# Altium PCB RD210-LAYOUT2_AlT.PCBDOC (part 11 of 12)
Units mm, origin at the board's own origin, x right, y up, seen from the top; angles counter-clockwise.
Board outline 250 x 123 mm, 4 copper layers (TOP, Mid-Layer 1, Mid-Layer 2, BOTTOM), stack 0.711 mm thick; 1043 components, 659 nets, 2786 pads, 1228 vias.
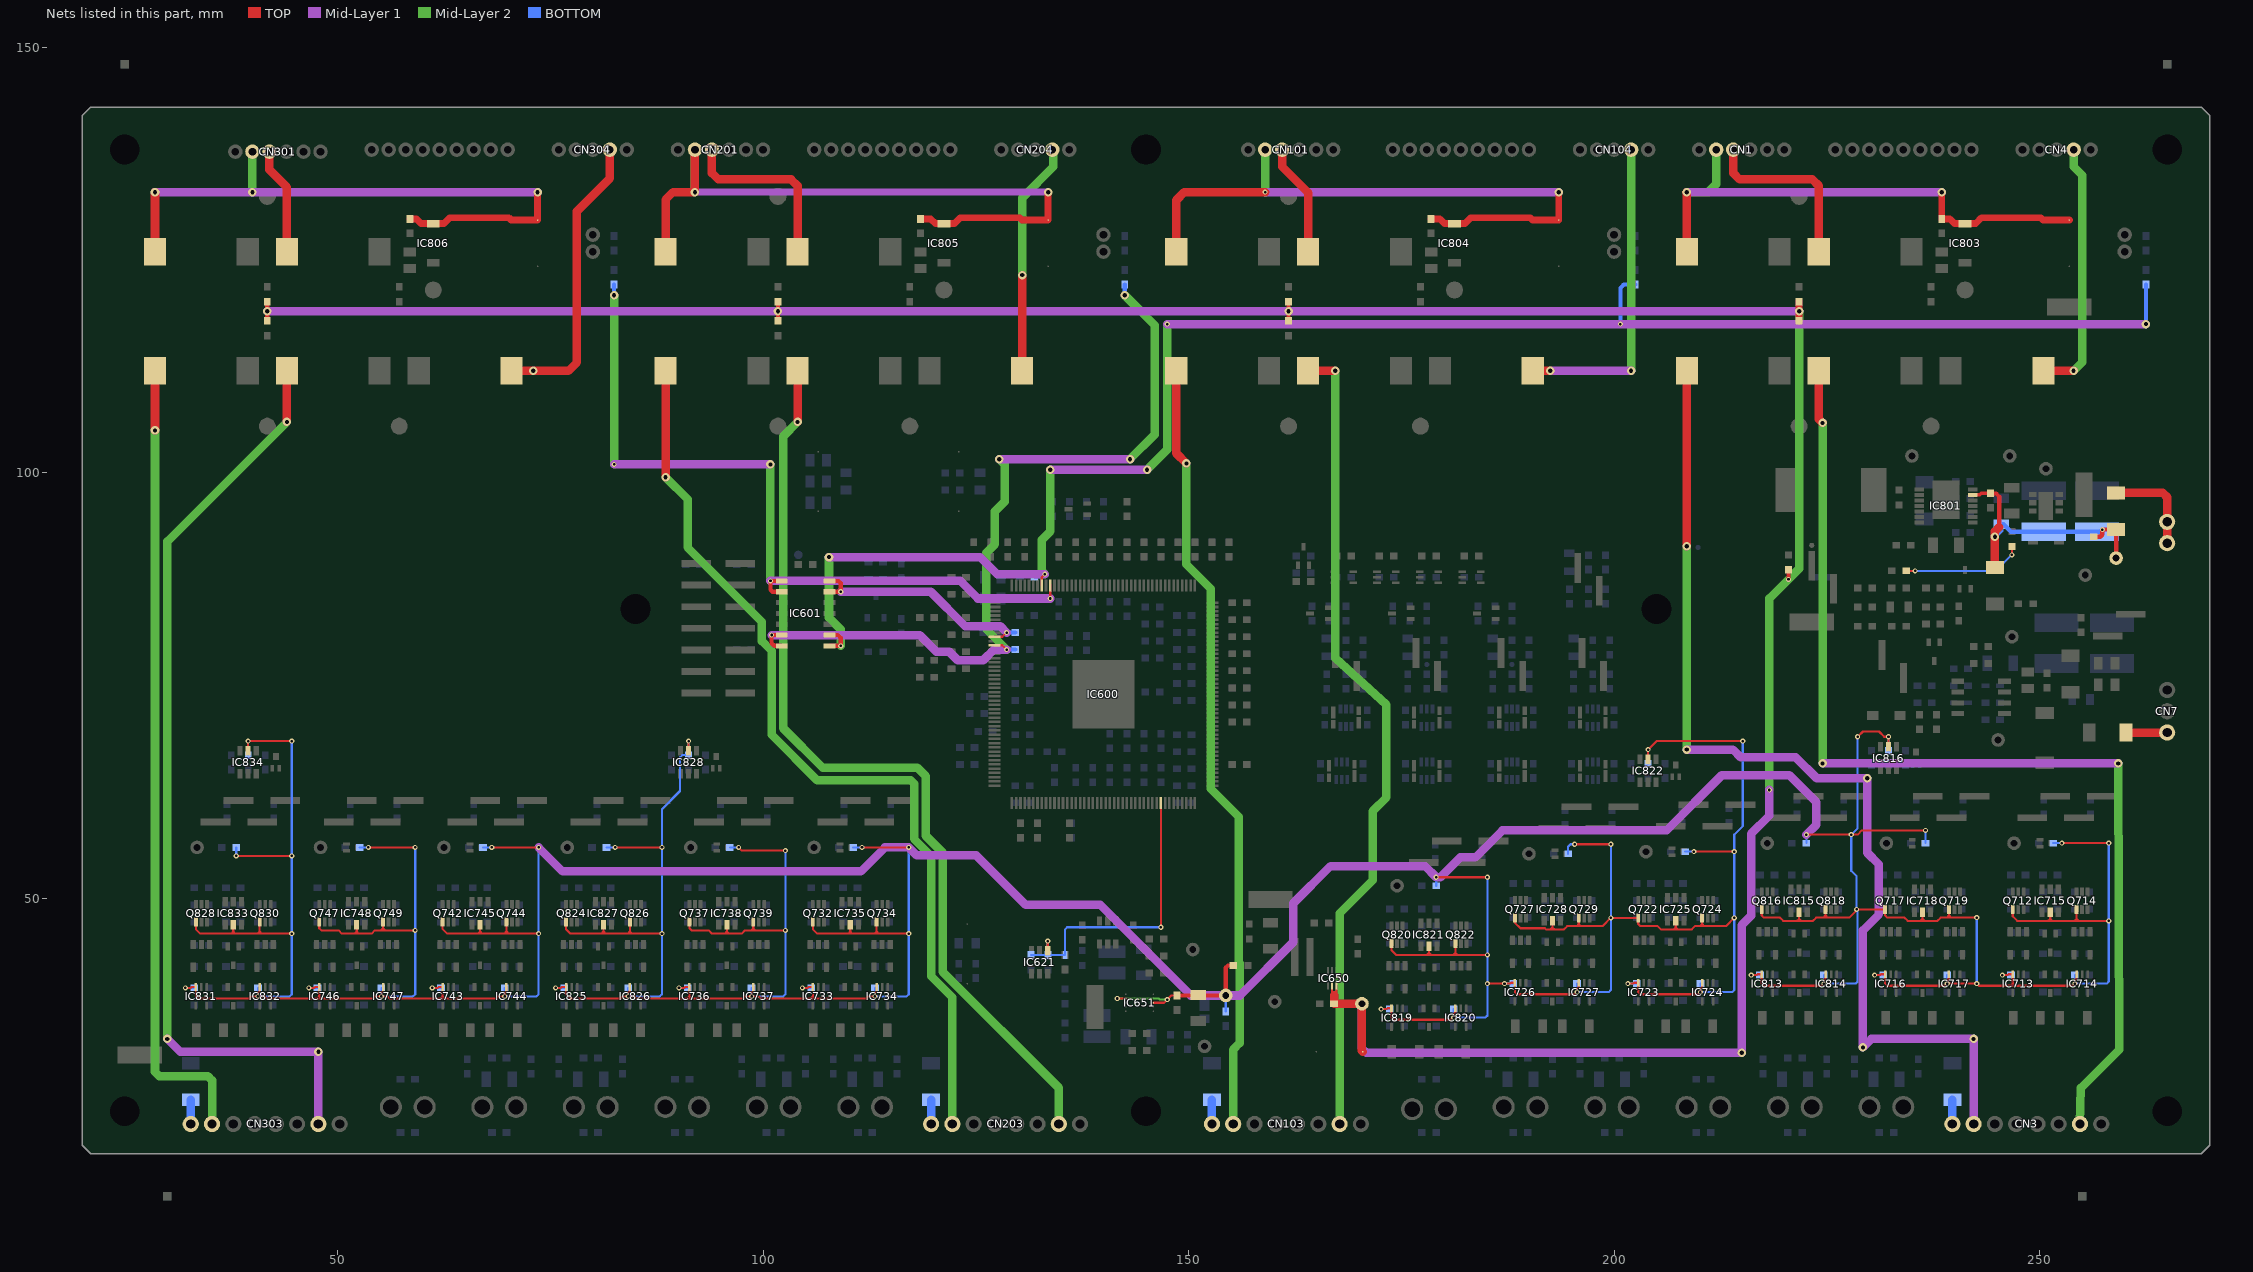
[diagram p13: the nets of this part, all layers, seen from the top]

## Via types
v1: diameter 0.6, hole 0.3, TOP to BOTTOM, 1134 vias
v2: diameter 1, hole 0.5, TOP to BOTTOM, 94 vias

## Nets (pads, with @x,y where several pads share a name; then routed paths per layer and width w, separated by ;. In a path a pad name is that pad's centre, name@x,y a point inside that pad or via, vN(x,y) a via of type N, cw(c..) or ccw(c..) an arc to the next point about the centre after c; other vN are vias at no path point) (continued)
VP_5R0-1234: ?.1 C701.2 C702.2 C716.1 C717.1 C718.1 C726.1 C727.1 C728.1 C736.1 C737.1 C738.1 C746.1 C747.1 C748.1 C756.1 C757.1 C758.1 C766.1 C767.1 C768.1 C776.1 C777.1 C778.1 C786.1 C787.1 C916.1 C917.1 C918.1 C919.1 C926.1 C927.1 C928.1 C929.1 C936.1 C937.1 C938.1 C939.1 C946.1 C947.1 C948.1 C949.1 CN959.1 IC651.3 IC651.7 IC713.3 IC714.3 IC715.5 IC716.3 IC717.3 IC718.5 IC723.3 IC724.3 IC725.5 IC726.3 IC727.3 IC728.5 IC733.3 IC734.3 IC735.5 IC736.3 IC737.3 IC738.5 IC743.3 IC744.3 IC745.5 IC746.3 IC747.3 IC748.5 IC813.3 IC814.3 IC815.5 IC816.5 IC819.3 IC820.3 IC821.5 IC822.5 IC825.3 IC826.3 IC827.5 IC828.5 IC831.3 IC832.3 IC833.5 IC834.5 J826.2 Q712.1 Q714.1 Q717.1 Q719.1 Q722.1 Q724.1 Q727.1 Q729.1 Q732.1 Q734.1 Q737.1 Q739.1 Q742.1 Q744.1 Q747.1 Q749.1 Q816.1 Q818.1 Q820.1 Q822.1 Q824.1 Q826.1 Q828.1 Q830.1 R674.1 | length 997.2
  TOP w0.25: v1(32.125,39.5) 32.775,39.5 32.875,39.6 IC831.3@33.35,39.6 33.35,38.5 33.6,38.25 39.625,38.25 39.875,38.5 v1(40.65,38.5) ; Q828.1@33.35,47.225 33.35,46.4 33.875,45.875 37.5,45.875 ; IC833.5@37.75,46.9 37.75,46.125 ; v1(38.1,55) v1(44.625,55) ; IC834.5@39.5,67.35 v1(39.5,68.5) v1(44.625,68.5) ; IC832.3@40.85,39.6 40.85,39.125 40.65,38.925 v1(40.65,38.5) ; Q830.1@40.85,47.225 40.85,46.125 ; v1(44.625,45.875) 41.1,45.875 ; v1(46.625,39.5) 47.275,39.5 47.375,39.6 IC746.3@47.85,39.6 47.85,38.5 ; Q747.1@47.85,47.225 47.85,46.5 48.1,46.25 50.125,46.25 50.5,45.875 52,45.875 ; IC748.5@52.25,46.9 52.25,46.125 ; v1(53.625,56) v1(59.125,56) ; IC747.3@55.35,39.6 55.35,39.125 55.15,38.925 v1(55.15,38.5) ; Q749.1@55.35,47.225 55.35,46.5 ; v1(59.125,46.25) 55.6,46.25 ; v1(61.125,39.5) 61.775,39.5 61.875,39.6 IC743.3@62.35,39.6 62.35,38.5 ; Q742.1@62.35,47.225 62.35,46.4 62.875,45.875 66.5,45.875 ; IC745.5@66.75,46.9 66.75,46.125 ; v1(68.125,56) v1(73.625,56) ; IC744.3@69.85,39.6 69.85,39.125 69.65,38.925 v1(69.65,38.5) 68.875,38.5 68.625,38.25 62.6,38.25 ; Q744.1@69.85,47.225 69.85,46.125 ; v1(73.625,45.875) 70.1,45.875 ; v1(75.625,39.5) 76.275,39.5 76.375,39.6 IC825.3@76.85,39.6 76.85,38.75 77.35,38.25 83.25,38.25 83.5,38.5 v1(84.15,38.5) ; Q824.1@76.85,47.225 76.85,46.4 77.375,45.875 81,45.875 ; IC827.5@81.25,46.9 81.25,46.125 ; v1(82.625,56) v1(88.125,56) ; IC826.3@84.35,39.6 84.35,39.125 84.15,38.925 v1(84.15,38.5) ; Q826.1@84.35,47.225 84.35,46.125 ; v1(88.125,45.875) 84.6,45.875 ; v1(90.125,39.5) 90.775,39.5 90.875,39.6 IC736.3@91.35,39.6 91.35,38.5 ; IC828.5@91.25,67.35 v1(91.25,68.5) ; Q737.1@91.35,47.225 91.35,46.5 91.6,46.25 93.625,46.25 94,45.875 95.5,45.875 ; IC738.5@95.75,46.9 95.75,46.125 ; v1(97.125,56) 97.5,55.625 v1(102.625,55.625) ; IC737.3@98.85,39.6 98.85,39.125 98.65,38.925 v1(98.65,38.5) ; Q739.1@98.85,47.225 98.85,46.5 ; v1(102.625,46.25) 99.1,46.25 ; v1(104.625,39.5) 105.275,39.5 105.375,39.6 IC733.3@105.85,39.6 105.85,38.5 ; Q732.1@105.85,47.225 105.85,46.4 106.375,45.875 110,45.875 ; IC735.5@110.25,46.9 110.25,46.125 ; v1(111.625,56) v1(117.125,56) ; IC734.3@113.35,39.6 113.35,39.125 113.15,38.925 v1(113.15,38.5) 112.375,38.5 112.125,38.25 106.1,38.25 ; Q734.1@113.35,47.225 113.35,46.125 ; v1(117.125,45.875) 113.6,45.875 ; v1(141.625,38.25) IC651.7@142.625,38.25 ; IC651.3@145.875,37.75 147.125,37.75 v1(147.5,38.125) 147.975,38.6 C702.2@148.625,38.6 ; C701.2@151.075,38.6 C701.2@151.125,38.65 ; v1(172.625,37) 173.275,37 173.375,37.1 IC819.3@173.85,37.1 173.85,36 174.1,35.75 180.9,35.75 v1(181.15,36) 181.15,36.425 181.35,36.625 IC820.3@181.35,37.1 ; Q820.1@173.85,44.725 173.85,43.9 174.375,43.375 178,43.375 ; IC821.5@178.25,44.4 178.25,43.625 ; v1(179.1,52.5) v1(185.125,52.5) ; Q822.1@181.35,44.725 181.35,43.625 ; v1(185.125,40) v1(187.125,40) 187.775,40 187.875,40.1 IC726.3@188.35,40.1 188.35,39 188.6,38.75 195.4,38.75 v1(195.65,39) 195.65,39.425 195.85,39.625 IC727.3@195.85,40.1 ; v1(185.125,43.375) 181.6,43.375 ; Q727.1@188.35,47.725 188.35,47.15 189,46.5 191.875,46.5 192,46.375 192.5,46.375 ; IC728.5@192.75,47.4 192.75,46.625 ; v1(195.375,56.375) v1(199.625,56.375) ; Q729.1@195.85,47.725 195.85,47 ; v1(201.625,40) 202.275,40 202.375,40.1 IC723.3@202.85,40.1 202.85,39 203.1,38.75 209.9,38.75 v1(210.15,39) 210.15,39.425 210.35,39.625 IC724.3@210.35,40.1 ; IC822.5@204,66.35 v1(204,67.5) 205,68.5 v1(215.125,68.5) ; IC725.5@207.25,47.4 207.25,46.625 ; v1(209.375,55.5) v1(214.125,55.5) ; Q724.1@210.35,47.725 210.35,47 ; v1(214.125,47.725) 213.15,46.75 210.6,46.75 ; v1(216.125,41) 216.775,41 216.875,41.1 IC813.3@217.35,41.1 217.35,40 217.6,39.75 224.4,39.75 v1(224.65,40) 224.65,40.425 224.85,40.625 IC814.3@224.85,41.1 ; Q816.1@217.35,48.725 217.35,48 217.6,47.75 219.5,47.75 219.875,47.375 221.5,47.375 ; IC815.5@221.75,48.4 221.75,47.625 ; v1(222.6,57.5) v1(227.875,57.5) 228.625,57.5 229.125,58 v1(236.6,58) ; Q818.1@224.85,48.725 224.85,48 ; v1(228.625,69) 229.25,69.625 231.125,69.625 231.75,69 v1(232.25,69) IC816.5@232.25,67.85 ; v1(230.625,41) 231.275,41 231.375,41.1 IC716.3@231.85,41.1 231.85,40 232.1,39.75 238.9,39.75 v1(239.15,40) ; IC718.5@236.25,48.4 236.25,47.625 ; IC717.3@239.35,41.1 239.35,40.625 239.15,40.425 v1(239.15,40) ; Q719.1@239.35,48.725 239.35,48 ; v1(242.625,47.75) 239.6,47.75 ; v1(245.625,41) 246.275,41 246.375,41.1 IC713.3@246.85,41.1 246.85,40 ; Q712.1@246.85,48.725 246.85,47.9 247.375,47.375 251,47.375 ; IC715.5@251.25,48.4 251.25,47.625 ; v1(252.625,56.5) v1(258.125,56.5) ; IC714.3@254.35,41.1 254.35,40.625 254.15,40.425 v1(254.15,40) 253.9,39.75 247.1,39.75 ; Q714.1@254.35,48.725 254.35,47.625 ; v1(258.125,47.375) 254.6,47.375 ; 37.5,45.875 38,45.875 ; 37.5,45.875 37.75,46.125 ; 37.75,46.125 38,45.875 ; 38,45.875 40.6,45.875 ; 40.6,45.875 41.1,45.875 ; 40.6,45.875 40.85,46.125 ; v1(40.65,38.5) 41.375,38.5 41.625,38.25 47.6,38.25 ; 40.85,46.125 41.1,45.875 ; 47.6,38.25 47.85,38.5 ; 47.6,38.25 48.1,38.25 ; 47.85,38.5 48.1,38.25 ; 48.1,38.25 54.125,38.25 54.375,38.5 v1(55.15,38.5) ; 52,45.875 52.25,46.125 ; 52,45.875 52.5,45.875 ; 52.25,46.125 52.5,45.875 ; 52.5,45.875 54,45.875 54.375,46.25 55.1,46.25 ; 55.1,46.25 55.6,46.25 ; 55.1,46.25 55.35,46.5 ; v1(55.15,38.5) 55.875,38.5 56.125,38.25 62.1,38.25 ; 55.35,46.5 55.6,46.25 ; 62.1,38.25 62.35,38.5 ; 62.1,38.25 62.6,38.25 ; 62.35,38.5 62.6,38.25 ; 66.5,45.875 67,45.875 ; 66.5,45.875 66.75,46.125 ; 66.75,46.125 67,45.875 ; 67,45.875 69.6,45.875 ; 69.6,45.875 70.1,45.875 ; 69.6,45.875 69.85,46.125 ; 69.85,46.125 70.1,45.875 ; 81,45.875 81.5,45.875 ; 81,45.875 81.25,46.125 ; 81.25,46.125 81.5,45.875 ; 81.5,45.875 84.1,45.875 ; 84.1,45.875 84.6,45.875 ; 84.1,45.875 84.35,46.125 ; v1(84.15,38.5) 84.875,38.5 85.125,38.25 91.1,38.25 ; 84.35,46.125 84.6,45.875 ; 91.1,38.25 91.35,38.5 ; 91.1,38.25 91.6,38.25 ; 91.35,38.5 91.6,38.25 ; 91.6,38.25 97.625,38.25 97.875,38.5 v1(98.65,38.5) ; 95.5,45.875 96,45.875 ; 95.5,45.875 95.75,46.125 ; 95.75,46.125 96,45.875 ; 96,45.875 97.5,45.875 97.875,46.25 98.6,46.25 ; 98.6,46.25 99.1,46.25 ; 98.6,46.25 98.85,46.5 ; v1(98.65,38.5) 99.5,38.5 99.75,38.25 105.6,38.25 ; 98.85,46.5 99.1,46.25 ; 105.6,38.25 105.85,38.5 ; 105.6,38.25 106.1,38.25 ; 105.85,38.5 106.1,38.25 ; 110,45.875 110.5,45.875 ; 110,45.875 110.25,46.125 ; 110.25,46.125 110.5,45.875 ; 110.5,45.875 113.1,45.875 ; 113.1,45.875 113.6,45.875 ; 113.1,45.875 113.35,46.125 ; 113.35,46.125 113.6,45.875 ; 178,43.375 178.5,43.375 ; 178,43.375 178.25,43.625 ; 178.25,43.625 178.5,43.375 ; 178.5,43.375 181.1,43.375 ; 181.1,43.375 181.6,43.375 ; 181.1,43.375 181.35,43.625 ; 181.35,43.625 181.6,43.375 ; 192.5,46.375 192.75,46.625 ; 192.5,46.375 193,46.375 ; 192.75,46.625 193,46.375 ; 193,46.375 194.125,46.375 194.5,46.75 195.6,46.75 ; 195.6,46.75 195.85,47 ; 195.6,46.75 196.1,46.75 ; 195.85,47 196.1,46.75 ; 196.1,46.75 198.65,46.75 v1(199.625,47.725) Q722.1@202.85,47.725 202.85,47 203.1,46.75 205.125,46.75 205.5,46.375 207,46.375 ; 207,46.375 207.5,46.375 ; 207,46.375 207.25,46.625 ; 207.25,46.625 207.5,46.375 ; 207.5,46.375 209.125,46.375 209.5,46.75 210.1,46.75 ; 210.1,46.75 210.6,46.75 ; 210.1,46.75 210.35,47 ; 210.35,47 210.6,46.75 ; 221.5,47.375 222,47.375 ; 221.5,47.375 221.75,47.625 ; 221.75,47.625 222,47.375 ; 222,47.375 223.375,47.375 223.75,47.75 224.6,47.75 ; 224.6,47.75 225.1,47.75 ; 224.6,47.75 224.85,48 ; 224.85,48 225.1,47.75 ; 225.1,47.75 227.65,47.75 228.5,48.6 v1(228.5,48.725) Q717.1@231.85,48.725 231.85,48 232.1,47.75 234.125,47.75 234.5,47.375 236,47.375 ; 236,47.375 236.5,47.375 ; 236,47.375 236.25,47.625 ; 236.25,47.625 236.5,47.375 ; 236.5,47.375 238,47.375 238.375,47.75 239.1,47.75 ; 239.1,47.75 239.6,47.75 ; 239.1,47.75 239.35,48 ; v1(239.15,40) v1(242.625,40) 242.875,39.75 246.6,39.75 ; 239.35,48 239.6,47.75 ; 246.6,39.75 246.85,40 ; 246.6,39.75 247.1,39.75 ; 246.85,40 247.1,39.75 ; 251,47.375 251.5,47.375 ; 251,47.375 251.25,47.625 ; 251.25,47.625 251.5,47.375 ; 251.5,47.375 254.1,47.375 ; 254.1,47.375 254.6,47.375 ; 254.1,47.375 254.35,47.625 ; 254.35,47.625 254.6,47.375
  TOP w0.5: C702.2@148.625,38.6 C701.2@151.075,38.6 ; C701.2@151.125,38.65 151.175,38.6 CN959.1@154.375,38.6 154.375,41.875 154.625,42.125 J826.2@155.25,42.125
  Mid-Layer 1 w1: v1(73.625,56) 76.445,53.18 111.504,53.18 114.324,56 v1(117.125,56) 118.04,55.085 125.025,55.085 130.871,49.239 139.638,49.239 150.277,38.6 CN959.1@154.375,38.6 156.042,38.6 162.304,44.861 162.304,49.433 166.685,53.815 177.785,53.815 v1(179.1,52.5) 179.594,52.5 181.925,54.831 183.703,54.831 186.878,58.006 206.182,58.006 212.659,64.483 220.597,64.483 223.772,61.308 223.772,58.672 v1(222.6,57.5)
  Mid-Layer 2 w0.25: v1(141.625,38.25) 146.5,38.25 146.625,38.125 v1(147.5,38.125)
  BOTTOM w0.25: v1(32.125,39.5) C946.1@33.15,39.5 ; v1(38.1,55) C948.1@38.1,56 ; C949.1@39.5,66.85 v1(39.5,68.5) ; C947.1@40.65,39.5 v1(40.65,38.5) 44.375,38.5 44.625,38.75 v1(44.625,45.875) v1(44.625,55) v1(44.625,68.5) ; v1(46.625,39.5) C786.1@47.65,39.5 ; ?.1@52.6,56 v1(53.625,56) ; C787.1@55.15,39.5 v1(55.15,38.5) 58.875,38.5 59.125,38.75 v1(59.125,46.25) v1(59.125,56) ; v1(61.125,39.5) C776.1@62.15,39.5 ; C778.1@67.1,56 v1(68.125,56) ; C777.1@69.65,39.5 v1(69.65,38.5) 73.375,38.5 73.625,38.75 v1(73.625,45.875) v1(73.625,56) ; v1(75.625,39.5) C936.1@76.65,39.5 ; C938.1@81.6,56 v1(82.625,56) ; C937.1@84.15,39.5 v1(84.15,38.5) 87.875,38.5 88.125,38.75 v1(88.125,45.875) v1(88.125,56) 88.125,60.5 90.25,62.625 90.25,66.6 90.5,66.85 C939.1@91.25,66.85 v1(91.25,68.5) ; v1(90.125,39.5) C766.1@91.15,39.5 ; C768.1@96.1,56 v1(97.125,56) ; C767.1@98.65,39.5 v1(98.65,38.5) 102.375,38.5 102.625,38.75 v1(102.625,46.25) v1(102.625,55.625) ; v1(104.625,39.5) C756.1@105.65,39.5 ; C758.1@110.6,56 v1(111.625,56) ; C757.1@113.15,39.5 v1(113.15,38.5) 116.875,38.5 117.125,38.75 v1(117.125,45.875) v1(117.125,56) ; R674.1@154.375,36.725 CN959.1@154.375,38.6 ; v1(172.625,37) C926.1@173.65,37 ; C928.1@179.1,51.5 v1(179.1,52.5) ; C927.1@181.15,37 v1(181.15,36) 184.875,36 185.125,36.25 v1(185.125,40) v1(185.125,43.375) v1(185.125,52.5) ; v1(187.125,40) C746.1@188.15,40 ; C748.1@194.6,55.25 194.6,56.1 194.875,56.375 v1(195.375,56.375) ; C747.1@195.65,40 v1(195.65,39) 199.375,39 199.625,39.25 v1(199.625,47.725) v1(199.625,56.375) ; v1(201.625,40) C736.1@202.65,40 ; C929.1@204,65.85 v1(204,67.5) ; C738.1@208.35,55.5 v1(209.375,55.5) ; C737.1@210.15,40 v1(210.15,39) 213.875,39 214.125,39.25 v1(214.125,47.725) v1(214.125,55.5) 214.125,57.5 215.125,58.5 v1(215.125,68.5) ; v1(216.125,41) C916.1@217.15,41 ; C918.1@222.6,56.5 v1(222.6,57.5) ; C917.1@224.65,41 v1(224.65,40) 228.375,40 228.625,40.25 228.625,48.6 v1(228.5,48.725) 228.5,52.625 227.875,53.25 v1(227.875,57.5) 228.625,58.25 v1(228.625,69) ; v1(230.625,41) C726.1@231.65,41 ; C919.1@232.25,67.35 v1(232.25,69) ; C728.1@236.6,56.5 v1(236.6,58) ; v1(239.15,40) C727.1@239.15,41 ; v1(242.625,40) v1(242.625,47.75) ; v1(245.625,41) C716.1@246.65,41 ; C718.1@251.6,56.5 v1(252.625,56.5) ; C717.1@254.15,41 v1(254.15,40) 257.875,40 258.125,40.25 v1(258.125,47.375) v1(258.125,56.5)
VP_5R0_SYS: J828.1 R817.2 | length 14.2
  TOP w0.25: R817.2@234.35,88.5 v1(235.375,88.5) ; v1(246.75,90.375) J828.1@246.75,91.375
  BOTTOM w0.25: v1(235.375,88.5) 244.875,88.5 v1(246.75,90.375)
VP_5V_I0_0: CN1.4 L810.2 | length 21.2
  TOP w1: CN1.4@214,138 214,135.25 214.75,134.5 223.3,134.5 224.05,133.75 L810.2@224.05,126
VP_5V_I0_1: CN3.2 L811.2 | length 125.3
  TOP w1: L811.2@224.05,112 224.05,106.325 v2(224.5,105.875)
  Mid-Layer 1 w1: v2(224.5,65.875) v2(259.25,65.875)
  Mid-Layer 2 w1: v2(224.5,65.875) v2(224.5,105.875) ; CN3.2@254.75,23.5 254.868,27.743 259.376,32.251 v2(259.25,65.875)
VP_5V_I0_2: CN4.2 L812.2 | length 30.4
  TOP w1: L812.2@250.45,112 v2(254,112)
  Mid-Layer 2 w1: v2(254,112) 255,113 255,135 254,136 CN4.2@254,138
VP_5V_I1_0: CN101.4 L813.2 | length 13.3
  TOP w1: CN101.4@161,138 161,136 164.05,132.95 L813.2@164.05,126
VP_5V_I1_1: CN103.2 L814.2 | length 96.6
  TOP w1: L814.2@164.05,112 v2(167.25,112)
  Mid-Layer 2 w1: v2(167.25,112) 167.25,78.228 173.25,72.75 173.25,61.875 171.625,60.25 171.625,52.125 167.75,48.25 CN103.2@167.75,23.5
VP_5V_I1_2: CN104.2 L815.2 | length 37.5
  TOP w1: L815.2@190.45,112 v2(192.5,112)
  Mid-Layer 1 w1: v2(192.5,112) v2(202,112)
  Mid-Layer 2 w1: v2(202,112) CN104.2@202,138
VP_5V_I2_0: CN201.4 L816.2 | length 21.2
  TOP w1: CN201.4@94,138 94,135.25 94.75,134.5 103.3,134.5 104.05,133.75 L816.2@104.05,126
VP_5V_I2_1: CN203.2 L817.2 | length 109.1
  TOP w1: v2(104.05,106) L817.2@104.05,112
  Mid-Layer 2 w1: v2(104.05,106) 102.375,104.325 102.375,70 107,65.375 118.125,65.375 119.125,64.375 119.125,57.375 121.125,55.375 121.125,41.375 134.75,27.75 CN203.2@134.75,23.5
VP_5V_I2_2: CN204.2 L818.2 | length 27.6
  TOP w1: L818.2@130.45,112 v2(130.45,123.25)
  Mid-Layer 2 w1: v2(130.45,123.25) 130.45,132.325 134.125,136 134.125,137.875 CN204.2@134,138
VP_5V_I3_0: CN301.4 L819.2 | length 12.6
  TOP w1: CN301.4@42,137.75 42,135.625 44.05,133.575 L819.2@44.05,126
VP_5V_I3_1: CN303.2 L820.2 | length 111.2
  TOP w1: v2(44.05,106) L820.2@44.05,112
  Mid-Layer 1 w1: v2(30,33.5) 31.5,32 v2(47.75,32) CN303.2@47.75,23.5
  Mid-Layer 2 w1: v2(30,33.5) 30,91.95 v2(44.05,106)
VP_5V_I3_2: CN304.2 L821.2 | length 34.7
  TOP w1: L821.2@70.45,112 v2(73,112) 77.125,112 78.125,113 78.125,130.75 82,134.625 CN304.2@82,138
VP_12R0_SYS: C650.1 C651.2 CN957.1 IC650.6 IC650.7 J802.2 J806.1 J807.1 J808.1 J809.1 J810.1 J811.1 J812.1 J813.1 | length 342.5
  TOP w0.25: IC650.6@166.875,39.75 166.875,38.85 167.1,38.625 167.375,38.9 IC650.7@167.375,39.75
  TOP w0.5: J813.1@41.75,117.875 v2(41.75,119) J812.1@41.75,120.125 ; J811.1@101.75,117.875 v2(101.75,119) J810.1@101.75,120.125 ; J809.1@161.75,117.875 v2(161.75,119) J808.1@161.75,120.125 ; v1(220.5,87.5) J802.2@220.5,88.625
  TOP w0.8: J807.1@221.75,117.875 v2(221.75,119) J806.1@221.75,120.125
  TOP w1: 167.1,38.625 C651.2@167.1,37.625 CN957.1@170.375,37.625 170.375,32.1 C650.1@170.475,32
  Mid-Layer 1 w1: v2(41.75,119) v2(101.75,119) v2(161.75,119) v2(221.75,119) ; CN957.1@170.375,37.625 170.375,32.375 170.875,31.875 v2(215,31.875) 215,46.875 216.125,48 216.125,57.625 218.25,59.75 v1(218.25,62.75)
  Mid-Layer 2 w1: v1(218.25,62.75) 218.25,85.25 v1(220.5,87.5) 221.75,88.75 v2(221.75,119)
VP_12R0_SYS_I0_0: C821.1 C825.2 CN1.5 IC803.1 L802.2 | length 63.6
  TOP w0.8: v2(238.5,133) C825.2@238.5,129.85 239.45,129.85 240,129.3 IC803.1@241.25,129.3 242.5,129.3 243.2,130 250.125,130 250.4,129.725 C821.1@253.5,129.725
  TOP w1: L802.2@208.55,126 v2(208.55,133)
  Mid-Layer 1 w1: v2(208.55,133) v2(238.5,133)
  Mid-Layer 2 w1: v2(208.55,133) 211.05,133 212,133.95 CN1.5@212,138
VP_12R0_SYS_I0_1: CN3.7 L806.2 | length 123.5
  TOP w1: v2(208.55,91.375) L806.2@208.55,112
  Mid-Layer 1 w1: v2(208.55,67.5) 213.96,67.5 214.882,66.578 221.359,66.578 223.812,64.125 v2(229.75,64.125) 229.75,55.375 231.125,54 231.125,48.125 229.25,46.25 v2(229.25,32.5) 230.25,33.5 v2(242.25,33.5) CN3.7@242.25,23.5
  Mid-Layer 2 w1: v2(208.55,67.5) v2(208.55,91.375)
VP_12R0_SYS_I1_0: C822.1 C826.2 CN101.5 IC804.1 L803.2 | length 75.3
  TOP w0.8: C826.2@178.5,129.85 179.525,129.85 180.075,129.3 IC804.1@181.25,129.3 182.5,129.3 183.2,130 190.125,130 190.4,129.725 C822.1@193.5,129.725 v2(193.5,133)
  TOP w1: L803.2@148.55,126 148.55,132.05 149.5,133 v1(159,133)
  Mid-Layer 1 w1: v1(159,133) v2(193.5,133)
  Mid-Layer 2 w1: v1(159,133) CN101.5@159,138
VP_12R0_SYS_I1_1: CN103.7 L807.2 | length 91.9
  TOP w1: L807.2@148.55,112 148.55,102.325 v2(149.75,101.125)
  Mid-Layer 2 w1: v2(149.75,101.125) 149.75,89.25 152.625,86.375 152.625,62.875 155.875,59.625 155.875,42.5 156,42.375 156,33 155.25,32.25 CN103.7@155.25,23.5
VP_12R0_SYS_I2_0: C823.1 C827.2 CN201.5 IC805.1 L804.2 | length 80.3
  TOP w0.8: C827.2@118.5,129.85 119.7,129.85 120.25,129.3 IC805.1@121.25,129.3 122.5,129.3 123.2,130 130.125,130 130.4,129.725 C823.1@133.5,129.725 v2(133.5,133)
  TOP w1: L804.2@88.55,126 88.55,132.125 89.425,133 v2(92,133) CN201.5@92,138
  Mid-Layer 1 w0.8: v2(92,133) v2(133.5,133)
  Mid-Layer 2 w1: v2(92,133) CN201.5@92,138
VP_12R0_SYS_I2_1: CN203.7 L808.2 | length 108.9
  TOP w1: v2(88.55,99.5) L808.2@88.55,112
  Mid-Layer 2 w1: v2(88.55,99.5) 91.125,96.925 91.125,91.25 99.875,82.5 99.875,80.25 101,79.125 101,69.25 106.375,63.875 117.375,63.875 117.75,63.5 117.75,57 119.75,55 119.75,40.875 122.25,38.375 CN203.7@122.25,23.5
VP_12R0_SYS_I3_0: C824.1 C828.2 CN301.5 IC806.1 L805.2 | length 75.6
  TOP w0.8: C828.2@58.5,129.85 59.275,129.85 59.825,129.3 IC806.1@61.25,129.3 62.5,129.3 63.2,130 70.125,130 70.4,129.725 C824.1@73.5,129.725 v2(73.5,133)
  TOP w1: L805.2@28.55,126 v2(28.55,133)
  Mid-Layer 1 w1: v2(28.55,133) v2(40,133) v2(73.5,133)
  Mid-Layer 2 w1: v2(40,133) CN301.5@40,137.75
VP_12R0_SYS_I3_1: CN303.7 L809.2 | length 94.6
  TOP w1: v2(28.55,105) L809.2@28.55,112
  Mid-Layer 2 w1: v2(28.55,105) 28.55,29.625 29.05,29.125 34.75,29.125 35.25,28.625 CN303.7@35.25,23.5
VP_H: CN6.1 CN6.2 D805.1 | length 11.6
  TOP w1: D805.1@259,97.65 264.5,97.65 265,97.15 CN6.2@265,94.25 CN6.1@265,91.75
VP_L: CN7.1 D800.1 | length 4.9
  TOP w1: D800.1@260.15,69.5 CN7.1@265,69.5
VP_L_0: CN3.8 D801.1 | length 2.9
  BOTTOM w1: CN3.8@239.75,23.5 D801.1@239.75,26.35
VP_L_1: CN103.8 D802.1 | length 2.9
  BOTTOM w1: CN103.8@152.75,23.5 D802.1@152.75,26.35
VP_L_2: CN203.8 D803.1 | length 2.9
  BOTTOM w1: CN203.8@119.75,23.5 D803.1@119.75,26.35
VP_L_3: CN303.8 D804.1 | length 2.9
  BOTTOM w1: CN303.8@32.75,23.5 D804.1@32.75,26.35
VP_SYS: C812.2 C836.2 C837.2 D805.2 D811.2 IC801.13 J801.2 R812.1 TP803.1 | length 32.7
  TOP w0.4: IC801.13@242.15,97.425 242.95,97.425 243.125,97.6 R812.1@244.25,97.6
  TOP w0.5: R812.1@244.25,97.6 244.9,97.6 245.25,97.25 245.25,93.625 ; J801.2@256.375,92.5 257.125,92.5 257.375,92.75 v1(257.375,93.35) D805.2@259,93.35 TP803.1@259,90
  TOP w1: D811.2@244.75,88.9 v2(244.75,92.5) 244.75,93.125 245.25,93.625
  BOTTOM w0.5: v2(244.75,92.5) 245.5,93.25 C812.2@245.5,93.975 245.775,93.975 246.65,93.1 C837.2@250.5,93.1 C836.2@256.75,93.1 257.125,93.1 v1(257.375,93.35)
VREF_A: IC600.37 IC601.1 IC601.2 R562.1 R572.1 R665.2 | length 211.8
  TOP w0.25: IC600.37@132.75,86.8 132.75,87.75 v1(133.125,88.125)
  TOP w0.5: IC601.1@107.9,79.69 v1(109.125,79.69) 109.125,80.625 108.79,80.96 IC601.2@107.9,80.96
  Mid-Layer 1 w1: v2(107.75,90.125) 125.5,90.125 127.5,88.125 v1(133.125,88.125) ; v2(133.75,100.375) v2(145.125,100.375) ; v1(147.5,117.5) v1(200.75,117.5) v2(262.5,117.5)
  Mid-Layer 2 w1: v2(107.75,90.125) 107.75,83 109.125,81.625 v1(109.125,79.69) ; v1(133.125,88.125) 132.75,88.5 132.75,92.125 133.75,93.125 v2(133.75,100.375) ; v2(145.125,100.375) 147.5,102.75 v1(147.5,117.5)
  BOTTOM w0.25: R665.2@131.85,87.75 132.75,87.75 v1(133.125,88.125)
  BOTTOM w0.5: v1(200.75,117.5) 200.75,121.75 201.15,122.15 R572.1@202.5,122.15 ; v2(262.5,117.5) R562.1@262.5,122.15
VREF_B: IC600.53 IC601.6 IC601.7 R664.1 | length 27.7
  TOP w0.25: IC600.53@127.2,80.75 128.125,80.75 v1(128.625,81.25)
  TOP w0.5: IC601.6@107.9,86.04 v1(109.125,86.04) 109.125,87.06 108.875,87.31 IC601.7@107.9,87.31
  Mid-Layer 1 w1: v1(109.125,86.04) 119.71,86.04 123.75,82 127.875,82 v1(128.625,81.25)
  BOTTOM w0.5: v1(128.625,81.25) R664.1@129.65,81.25
VREF_C: IC600.35 IC601.8 IC601.9 R592.1 R663.2 | length 94
  TOP w0.25: v1(133.75,85.25) IC600.35@133.75,86.8
  TOP w0.5: IC601.9@102.1,86.04 101.125,86.04 100.875,86.29 v1(100.875,87.31) IC601.8@102.1,87.31
  Mid-Layer 1 w1: v1(82.5,101) v2(100.875,101) ; v1(100.875,87.31) 123.19,87.31 125.25,85.25 v1(133.75,85.25)
  Mid-Layer 2 w1: v1(82.5,101) v2(82.5,120.875) ; v1(100.875,87.31) v2(100.875,101)
  BOTTOM w0.25: R663.2@131.85,85.25 v1(133.75,85.25)
  BOTTOM w0.5: v2(82.5,120.875) R592.1@82.5,122.15
VREF_D: IC600.55 IC601.13 IC601.14 R582.1 R662.1 | length 98.4
  TOP w0.25: IC600.55@127.2,79.75 128.125,79.75 v1(128.625,79.25)
  TOP w0.5: IC601.14@102.1,79.69 101.31,79.69 101,80 v1(101,80.96) IC601.13@102.1,80.96
  Mid-Layer 1 w1: v1(101,80.96) 118.415,80.96 120.375,79 121.875,79 122.875,78 125.875,78 127.125,79.25 v1(128.625,79.25) ; v2(127.75,101.625) v2(143.125,101.625)
  Mid-Layer 2 w1: v2(127.75,101.625) 128.375,101 128.375,96.625 127.25,95.5 127.25,91.625 126.25,90.625 126.25,81.625 v1(128.625,79.25) ; v2(142.5,120.875) 146,117.375 146,104.5 v2(143.125,101.625)
  BOTTOM w0.5: v1(128.625,79.25) R662.1@129.65,79.25 ; v2(142.5,120.875) R582.1@142.5,122.15
XRS_N: C622.2 D620.1 IC600.124 IC621.1 R633.1 | length 35.8
  TOP w0.25: IC621.1@133.45,43.85 v1(133.45,45) ; v1(146.75,46.625) IC600.124@146.75,61.2
  BOTTOM w0.25: C622.2@131.5,43.35 R633.1@133.5,43.35 ; v1(133.45,45) 133.45,43.4 R633.1@133.5,43.35 ; v1(146.75,46.625) 135.75,46.625 135.5,46.375 D620.1@135.5,43.35 R633.1@133.5,43.35
pads on no net: CN2.3 CN2.4 CN2.5 CN7.2 CN102.3 CN102.4 CN102.5 CN202.3 CN202.4 CN202.5 CN302.3 CN302.4 CN302.5 CN620.6 IC106.1 IC600.73 IC600.74 IC600.92 IC600.121 IC602.3 IC620.6 IC621.6 IC650.2 IC710.1 IC710.2 IC711.1 IC711.2 IC712.1 IC712.2 IC719.1 IC719.2 IC720.1 IC720.2 IC721.1 IC721.2 IC722.1 IC722.2 IC729.1 IC729.2 IC730.1 IC730.2 IC731.1 IC731.2 IC732.1 IC732.2 IC739.1 IC739.2 IC740.1 IC740.2 IC741.1 IC741.2 IC742.1 IC742.2 IC749.1 IC749.2 IC801.1 IC801.7 IC801.8 IC801.14 IC802.4 IC807.1 IC808.1 IC809.1 IC811.1 IC811.2 IC812.1 IC812.2 IC817.1 IC817.2 IC818.1 IC818.2 IC823.1 IC823.2 IC824.1 IC824.2 IC829.1 IC829.2 IC830.1 IC830.2

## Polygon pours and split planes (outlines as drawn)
no net on TOP "TOP1" (solid, pour order 61): 126.5,87 ccw(c127,87) 127.5,87 ccw(c127,87)
no net on TOP "TOP2" (solid, pour order 62): 152.5,61 ccw(c153,61) 153.5,61 ccw(c153,61)
no net on TOP "TOP3" (solid, pour order 63): 41 vertices, not listed, extent 21,11 269,19
no net on TOP "TOP4" (solid, pour order 64): 41 vertices, not listed, extent 21,144 269,152
AGND on TOP "TOP5" (solid, pour order 65): 156 vertices, not listed, extent 126.323,81.1 132.799,85.8
AGND on TOP "TOP6" (solid, pour order 66): 126 vertices, not listed, extent 132.175,81.1 135.4,87.625
GND on TOP "TOP7" (solid, pour order 67): 37 vertices, not listed, extent 165.375,39.325 166.5,40.25
GND_P0 on TOP "TOP8" (solid, pour order 68): 668 vertices, not listed, extent 229,64 255.4,82
GND_P0 on TOP "TOP9" (solid, pour order 69): 517 vertices, not listed, extent 244.343,21 269,82
DGND on TOP "TOP10" (solid, pour order 70): 37 vertices, not listed, extent 154.075,92.55 155.425,94.824
DGND on TOP "TOP11" (solid, pour order 71): 38 vertices, not listed, extent 152.075,92.55 153.425,95.125
DGND on TOP "TOP12" (solid, pour order 72): 231 vertices, not listed, extent 152.326,78.325 157.8,86.699
DGND on TOP "TOP13" (solid, pour order 73): 504 vertices, not listed, extent 159.106,44.375 171.375,68.919
DGND on TOP "TOP14" (solid, pour order 74): 1809 vertices, not listed, extent 163.95,53.45 198.5,73.625
DGND on TOP "TOP15" (solid, pour order 75): 484 vertices, not listed, extent 155.57,69.051 160.675,77.224
DGND on TOP "TOP16" (solid, pour order 76): 369 vertices, not listed, extent 118.5,33.5 127.55,55.574
DGND on TOP "TOP17" (solid, pour order 77): 129 vertices, not listed, extent 128.675,54.926 130.793,57.554
DGND on TOP "TOP18" (solid, pour order 78): 1108 vertices, not listed, extent 90.25,75 110.925,101.5
DGND on TOP "TOP19" (solid, pour order 79): 793 vertices, not listed, extent 117.825,81.325 124.375,101.5
DGND on TOP "TOP20" (solid, pour order 80): 3573 vertices, not listed, extent 128.1,62.1 151.9,84.375
DGND on TOP "TOP21" (solid, pour order 81): 95 vertices, not listed, extent 130.075,52.801 133.3,57.399
DGND on TOP "TOP22" (solid, pour order 82): 89 vertices, not listed, extent 130.9,56.571 133.05,58.2
DGND on TOP "TOP23" (solid, pour order 83): 77 vertices, not listed, extent 145.825,89.051 147.175,95.125
DGND on TOP "TOP24" (solid, pour order 84): 37 vertices, not listed, extent 150.075,92.55 151.425,95.125
DGND on TOP "TOP25" (solid, pour order 85): 37 vertices, not listed, extent 148.325,92.55 149.425,95.125
DGND on TOP "TOP26" (solid, pour order 86): 92 vertices, not listed, extent 142.325,91.445 145.175,95.875
DGND on TOP "TOP28" (solid, pour order 88): 138.331,47.352 ccw(c138.406,47.352) 138.481,47.352 ccw(c138.406,47.352)
DGND on TOP "TOP29" (solid, pour order 89): 4464 vertices, not listed, extent 128.2,31 161.75,66.925
GND on TOP "TOP27" (solid, pour order 87): 16014 vertices, not listed, extent 21,21 267.5,142
no net on Mid-Layer 1 "MID130" (solid, pour order 46): 41 vertices, not listed, extent 21,11 269,19
no net on Mid-Layer 1 "MID131" (solid, pour order 47): 41 vertices, not listed, extent 21,144 269,152
GND on Mid-Layer 1 "MID132" (solid, pour order 48): 92 vertices, not listed, extent 250.75,22 253.75,23.162
GND on Mid-Layer 1 "MID133" (solid, pour order 49): 413 vertices, not listed, extent 48.45,23.838 241.55,29.9
GND on Mid-Layer 1 "MID134" (solid, pour order 50): 553 vertices, not listed, extent 150.306,136.63 198.048,139.55
GND on Mid-Layer 1 "MID135" (solid, pour order 51): 342 vertices, not listed, extent 128.7,136.63 139.694,139.55
GND on Mid-Layer 1 "MID136" (solid, pour order 52): 824 vertices, not listed, extent 76.7,136.7 130.048,139.55
GND on Mid-Layer 1 "MID137" (solid, pour order 53): 92 vertices, not listed, extent 130.75,22 133.75,23.162
GND on Mid-Layer 1 "MID138" (solid, pour order 54): 92 vertices, not listed, extent 163.75,22 166.75,23.162
GND_P0 on Mid-Layer 1 "MID139" (solid, pour order 55): 921 vertices, not listed, extent 48.75,21 269,82
DGND on Mid-Layer 1 "MID140" (solid, pour order 56): 347 vertices, not listed, extent 103.75,97.046 122.072,101.75
DGND on Mid-Layer 1 "MID141" (solid, pour order 57): 244.475,32.5 cw(c244.475,32.575) 244.4,32.575 244.4,50.772 244.4,50.775 244.4,50.778 244.4,64.5 ccw(c243.75,64.5) 244.038,65.083 cw(c244.071,65.15) 244.071,65.225 258.728,65.225 cw(c258.728,65.15) 258.802,65.15 258.802,39.241 cw(c258.728,39.241) 258.781,39.188 252.114,32.522 cw(c252.061,32.575) 252.061,32.5
DGND on Mid-Layer 1 "MID142" (solid, pour order 58): 42 vertices, not listed, extent 229.9,34.096 243.504,65.225
GND on Mid-Layer 1 "MID143" (solid, pour order 59): 7164 vertices, not listed, extent 21,21 267.5,142
DGND on Mid-Layer 1 "MID144" (solid, pour order 60): 3584 vertices, not listed, extent 32.575,32.5 230.475,98.5
no net on Mid-Layer 2 "MID245" (solid, pour order 27): 41 vertices, not listed, extent 21,144 269,152
no net on Mid-Layer 2 "MID246" (solid, pour order 28): 41 vertices, not listed, extent 21,11 269,19
GND on Mid-Layer 2 "MID247" (solid, pour order 29): 92 vertices, not listed, extent 163.75,22 166.75,23.162
GND on Mid-Layer 2 "MID248" (solid, pour order 30): 113 vertices, not listed, extent 156,23.838 167,29
DGND on Mid-Layer 2 "MID249" (solid, pour order 31): 619 vertices, not listed, extent 150.45,72.292 154.45,95.25
DGND on Mid-Layer 2 "MID250" (solid, pour order 32): 2460 vertices, not listed, extent 132.25,32.5 155.3,95.875
DGND on Mid-Layer 2 "MID251" (solid, pour order 33): 893 vertices, not listed, extent 153.325,32.5 172.55,95.25
GND on Mid-Layer 2 "MID252" (solid, pour order 34): 41 vertices, not listed, extent 168.5,25.5 173.75,29
GND on Mid-Layer 2 "MID253" (solid, pour order 35): 110 vertices, not listed, extent 135.5,24.75 154.5,29
GND_P0 on Mid-Layer 2 "MID254" (solid, pour order 36): 361 vertices, not listed, extent 235,21 269,82
GND on Mid-Layer 2 "MID255" (solid, pour order 37): 270 vertices, not listed, extent 236.5,21 255.25,28.25
GND_P0 on Mid-Layer 2 "MID256" (solid, pour order 38): 357 vertices, not listed, extent 135.75,21 173.75,25
GND on Mid-Layer 2 "MID257" (solid, pour order 39): 184 vertices, not listed, extent 116.5,21 135.25,29
GND on Mid-Layer 2 "MID258" (solid, pour order 40): 115 vertices, not listed, extent 123,23.839 134,29
DGND on Mid-Layer 2 "MID259" (solid, pour order 41): 122.975,29.494 cw(c122.975,29.569) 122.9,29.569 122.9,37.865 cw(c122.975,37.865) 122.975,37.94 123.61,37.94 cw(c123.61,37.865) 123.663,37.918 131.958,29.622 cw(c131.905,29.569) 131.905,29.494
DGND on Mid-Layer 2 "MID260" (solid, pour order 42): 422 vertices, not listed, extent 103.248,74.706 123.425,101.75
DGND on Mid-Layer 2 "MID261" (solid, pour order 43): 655 vertices, not listed, extent 168.59,21 258.5,72.5
GND on Mid-Layer 2 "MID262" (solid, pour order 44): 6554 vertices, not listed, extent 21,21 267.5,142
DGND on Mid-Layer 2 "MID263" (solid, pour order 45): 245 vertices, not listed, extent 30.75,21 121.5,66.959
no net on BOTTOM "BOTTOM64" (solid, pour order 2): 41 vertices, not listed, extent 21,11 269,19
no net on BOTTOM "BOTTOM65" (solid, pour order 3): 41 vertices, not listed, extent 21,144 269,152
GND on BOTTOM "BOTTOM66" (solid, pour order 4): 103 vertices, not listed, extent 250.75,21 254.5,23.161
GND on BOTTOM "BOTTOM67" (solid, pour order 5): 275 vertices, not listed, extent 131.676,93.75 140.258,97.175
GND on BOTTOM "BOTTOM68" (solid, pour order 6): 1418 vertices, not listed, extent 159.375,68.5 209.55,92.925
GND on BOTTOM "BOTTOM69" (solid, pour order 7): 90 vertices, not listed, extent 130.75,21 133.75,23.162
GND on BOTTOM "BOTTOM70" (solid, pour order 8): 579 vertices, not listed, extent 130.125,21 172,31.5
AGND on BOTTOM "BOTTOM71" (solid, pour order 9): 277 vertices, not listed, extent 132.138,76 135.876,84.925
AGND on BOTTOM "BOTTOM72" (solid, pour order 10): 2339 vertices, not listed, extent 103.5,75 141.5,93.125
DGND on BOTTOM "BOTTOM73" (solid, pour order 11): 365 vertices, not listed, extent 193.825,62.125 198.625,67.675
DGND on BOTTOM "BOTTOM74" (solid, pour order 12): 578 vertices, not listed, extent 183.801,62.125 190.883,67.675
DGND on BOTTOM "BOTTOM75" (solid, pour order 13): 532 vertices, not listed, extent 174.325,62.125 181.274,67.675
DGND on BOTTOM "BOTTOM76" (solid, pour order 14): 955 vertices, not listed, extent 163.575,62.2 172.175,73.425
DGND on BOTTOM "BOTTOM77" (solid, pour order 15): 213 vertices, not listed, extent 165.117,63.53 170.883,66.47
DGND on BOTTOM "BOTTOM78" (solid, pour order 16): 363 vertices, not listed, extent 193.676,66.901 198.625,73.425
DGND on BOTTOM "BOTTOM79" (solid, pour order 17): 781 vertices, not listed, extent 173.325,65.072 182.05,73.425
DGND on BOTTOM "BOTTOM80" (solid, pour order 18): 956 vertices, not listed, extent 183.2,63.701 193.175,73.5
DGND on BOTTOM "BOTTOM81" (solid, pour order 19): 655 vertices, not listed, extent 99.625,95.575 122.375,102.75
DGND on BOTTOM "BOTTOM82" (solid, pour order 20): 746 vertices, not listed, extent 142.125,84.9 158.75,93.25
DGND on BOTTOM "BOTTOM83" (solid, pour order 21): 2445 vertices, not listed, extent 150.453,59.45 167.675,89.925
DGND on BOTTOM "BOTTOM84" (solid, pour order 22): 5010 vertices, not listed, extent 109.047,55.2 152.3,85.574
DGND on BOTTOM "BOTTOM85" (solid, pour order 23): 4596 vertices, not listed, extent 99.625,32.125 155.675,91.925
DGND on BOTTOM "BOTTOM86" (solid, pour order 24): 811 vertices, not listed, extent 152.176,32.125 171.375,53.8
GND_P0 on BOTTOM "BOTTOM87" (solid, pour order 25): 537 vertices, not listed, extent 244.875,21 269,83.75
GND on BOTTOM "BOTTOM88" (solid, pour order 26): 16159 vertices, not listed, extent 21,21 267.5,142
no net on Top Overlay "TOPOVERLAY89" (solid, pour order 0): 123.175,39.586 cw(c124,43.5) 121.193,40.65 123.175,40.65
no net on Top Overlay "TOPOVERLAY90" (solid, pour order 0): 124.825,40.65 126.807,40.65 cw(c124,43.5) 124.825,39.586
no net on Top Overlay "TOPOVERLAY91" (solid, pour order 0): 122.175,95.086 cw(c123,99) 120.193,96.15 122.175,96.15
no net on Top Overlay "TOPOVERLAY92" (solid, pour order 0): 123.825,96.15 125.807,96.15 cw(c123,99) 123.825,95.086
no net on Top Overlay "TOPOVERLAY93" (solid, pour order 0): 105.675,95.086 cw(c106.5,99) 103.693,96.15 105.675,96.15
no net on Top Overlay "TOPOVERLAY94" (solid, pour order 0): 107.325,96.15 109.307,96.15 cw(c106.5,99) 107.325,95.086
no net on Top Overlay "TOPOVERLAY95" (solid, pour order 0): 254.175,125 255.934,125 cw(c253.5,127) 254.175,123.923
no net on Top Overlay "TOPOVERLAY96" (solid, pour order 0): 252.825,123.923 cw(c253.5,127) 251.066,125 252.825,125
no net on Top Overlay "TOPOVERLAY97" (solid, pour order 0): 194.175,125 195.934,125 cw(c193.5,127) 194.175,123.923
no net on Top Overlay "TOPOVERLAY98" (solid, pour order 0): 192.825,123.923 cw(c193.5,127) 191.066,125 192.825,125
no net on Top Overlay "TOPOVERLAY99" (solid, pour order 0): 134.175,125 135.934,125 cw(c133.5,127) 134.175,123.923
no net on Top Overlay "TOPOVERLAY100" (solid, pour order 0): 132.825,123.923 cw(c133.5,127) 131.066,125 132.825,125
no net on Top Overlay "TOPOVERLAY101" (solid, pour order 0): 74.175,125 75.934,125 cw(c73.5,127) 74.175,123.923
no net on Top Overlay "TOPOVERLAY102" (solid, pour order 0): 72.825,123.923 cw(c73.5,127) 71.066,125 72.825,125
no net on Top Overlay "TOPOVERLAY103" (solid, pour order 0): 257,20.675 ccw(c257.25,20.675) 257.5,20.675 ccw(c257.25,20.675)
no net on Top Overlay "TOPOVERLAY104" (solid, pour order 0): 261.9,91.75 ccw(c262.15,91.75) 262.4,91.75 ccw(c262.15,91.75)
no net on Top Overlay "TOPOVERLAY105" (solid, pour order 0): 170,20.675 ccw(c170.25,20.675) 170.5,20.675 ccw(c170.25,20.675)
no net on Top Overlay "TOPOVERLAY106" (solid, pour order 0): 137,20.675 ccw(c137.25,20.675) 137.5,20.675 ccw(c137.25,20.675)
no net on Top Overlay "TOPOVERLAY107" (solid, pour order 0): 50,20.675 ccw(c50.25,20.675) 50.5,20.675 ccw(c50.25,20.675)
no net on Top Overlay "TOPOVERLAY108" (solid, pour order 0): 180.95,88.4 ccw(c181.2,88.4) 181.45,88.4 ccw(c181.2,88.4)
no net on Top Overlay "TOPOVERLAY109" (solid, pour order 0): 108.75,79.125 ccw(c109,79.125) 109.25,79.125 ccw(c109,79.125)
no net on Top Overlay "TOPOVERLAY110" (solid, pour order 0): 139.3,43.6 ccw(c139.55,43.6) 139.8,43.6 ccw(c139.55,43.6)
no net on Top Overlay "TOPOVERLAY111" (solid, pour order 0): 133.75,44.875 ccw(c134,44.875) 134.25,44.875 ccw(c134,44.875)
no net on Top Overlay "TOPOVERLAY112" (solid, pour order 0): 168.075,42.15 ccw(c168.225,42.15) 168.375,42.15 ccw(c168.225,42.15)
no net on Top Overlay "TOPOVERLAY113" (solid, pour order 0): 146.55,36.75 ccw(c146.8,36.75) 147.05,36.75 ccw(c146.8,36.75)
no net on Top Overlay "TOPOVERLAY114" (solid, pour order 0): 252.85,94.95 ccw(c253.05,94.95) 253.25,94.95 ccw(c253.05,94.95)
no net on Top Overlay "TOPOVERLAY115" (solid, pour order 0): 218.243,123.755 ccw(c214,126) 218.44,124.175 218.869,124.175 cw(c214,126) 218.538,123.46
no net on Top Overlay "TOPOVERLAY116" (solid, pour order 0): 213.85,120.802 cw(c214,126) 209.131,124.175 209.56,124.175 ccw(c214,126) 213.849,121.202 213.85,121.202
no net on Top Overlay "TOPOVERLAY117" (solid, pour order 0): 218.44,127.825 ccw(c214,126) 214.15,130.798 214.15,131.198 cw(c214,126) 218.869,127.825
no net on Top Overlay "TOPOVERLAY118" (solid, pour order 0): 209.131,127.825 cw(c214,126) 209.462,128.54 209.757,128.245 ccw(c214,126) 209.56,127.825
no net on Top Overlay "TOPOVERLAY119" (solid, pour order 0): 158.243,123.755 ccw(c154,126) 158.44,124.175 158.869,124.175 cw(c154,126) 158.538,123.46
no net on Top Overlay "TOPOVERLAY120" (solid, pour order 0): 153.85,120.802 cw(c154,126) 149.131,124.175 149.56,124.175 ccw(c154,126) 153.849,121.202 153.85,121.202
no net on Top Overlay "TOPOVERLAY121" (solid, pour order 0): 158.44,127.825 ccw(c154,126) 154.15,130.798 154.15,131.198 cw(c154,126) 158.869,127.825
no net on Top Overlay "TOPOVERLAY122" (solid, pour order 0): 149.131,127.825 cw(c154,126) 149.462,128.54 149.757,128.245 ccw(c154,126) 149.56,127.825
no net on Top Overlay "TOPOVERLAY123" (solid, pour order 0): 98.243,123.755 ccw(c94,126) 98.44,124.175 98.869,124.175 cw(c94,126) 98.538,123.46
no net on Top Overlay "TOPOVERLAY124" (solid, pour order 0): 93.85,120.802 cw(c94,126) 89.131,124.175 89.56,124.175 ccw(c94,126) 93.849,121.202 93.85,121.202
no net on Top Overlay "TOPOVERLAY125" (solid, pour order 0): 98.44,127.825 ccw(c94,126) 94.15,130.798 94.15,131.198 cw(c94,126) 98.869,127.825
no net on Top Overlay "TOPOVERLAY126" (solid, pour order 0): 89.131,127.825 cw(c94,126) 89.462,128.54 89.757,128.245 ccw(c94,126) 89.56,127.825
no net on Top Overlay "TOPOVERLAY127" (solid, pour order 0): 38.243,123.755 ccw(c34,126) 38.44,124.175 38.869,124.175 cw(c34,126) 38.538,123.46
no net on Top Overlay "TOPOVERLAY128" (solid, pour order 0): 33.85,120.802 cw(c34,126) 29.131,124.175 29.56,124.175 ccw(c34,126) 33.849,121.202 33.85,121.202
no net on Top Overlay "TOPOVERLAY129" (solid, pour order 0): 38.44,127.825 ccw(c34,126) 34.15,130.798 34.15,131.198 cw(c34,126) 38.869,127.825
no net on Top Overlay "TOPOVERLAY130" (solid, pour order 0): 29.131,127.825 cw(c34,126) 29.462,128.54 29.757,128.245 ccw(c34,126) 29.56,127.825
no net on Top Overlay "TOPOVERLAY131" (solid, pour order 0): 218.243,109.755 ccw(c214,112) 218.44,110.175 218.869,110.175 cw(c214,112) 218.538,109.46
no net on Top Overlay "TOPOVERLAY132" (solid, pour order 0): 213.85,106.802 cw(c214,112) 209.131,110.175 209.56,110.175 ccw(c214,112) 213.849,107.202 213.85,107.202
no net on Top Overlay "TOPOVERLAY133" (solid, pour order 0): 218.44,113.825 ccw(c214,112) 214.15,116.798 214.15,117.198 cw(c214,112) 218.869,113.825
no net on Top Overlay "TOPOVERLAY134" (solid, pour order 0): 209.131,113.825 cw(c214,112) 209.462,114.54 209.757,114.245 ccw(c214,112) 209.56,113.825
no net on Top Overlay "TOPOVERLAY135" (solid, pour order 0): 158.243,109.755 ccw(c154,112) 158.44,110.175 158.869,110.175 cw(c154,112) 158.538,109.46
no net on Top Overlay "TOPOVERLAY136" (solid, pour order 0): 153.85,106.802 cw(c154,112) 149.131,110.175 149.56,110.175 ccw(c154,112) 153.849,107.202 153.85,107.202
no net on Top Overlay "TOPOVERLAY137" (solid, pour order 0): 158.44,113.825 ccw(c154,112) 154.15,116.798 154.15,117.198 cw(c154,112) 158.869,113.825
no net on Top Overlay "TOPOVERLAY138" (solid, pour order 0): 149.131,113.825 cw(c154,112) 149.462,114.54 149.757,114.245 ccw(c154,112) 149.56,113.825
no net on Top Overlay "TOPOVERLAY139" (solid, pour order 0): 98.243,109.755 ccw(c94,112) 98.44,110.175 98.869,110.175 cw(c94,112) 98.538,109.46
no net on Top Overlay "TOPOVERLAY140" (solid, pour order 0): 93.85,106.802 cw(c94,112) 89.131,110.175 89.56,110.175 ccw(c94,112) 93.849,107.202 93.85,107.202
no net on Top Overlay "TOPOVERLAY141" (solid, pour order 0): 98.44,113.825 ccw(c94,112) 94.15,116.798 94.15,117.198 cw(c94,112) 98.869,113.825
no net on Top Overlay "TOPOVERLAY142" (solid, pour order 0): 89.131,113.825 cw(c94,112) 89.462,114.54 89.757,114.245 ccw(c94,112) 89.56,113.825
no net on Top Overlay "TOPOVERLAY143" (solid, pour order 0): 38.243,109.755 ccw(c34,112) 38.44,110.175 38.869,110.175 cw(c34,112) 38.538,109.46
no net on Top Overlay "TOPOVERLAY144" (solid, pour order 0): 33.85,106.802 cw(c34,112) 29.131,110.175 29.56,110.175 ccw(c34,112) 33.849,107.202 33.85,107.202
no net on Top Overlay "TOPOVERLAY145" (solid, pour order 0): 38.44,113.825 ccw(c34,112) 34.15,116.798 34.15,117.198 cw(c34,112) 38.869,113.825
no net on Top Overlay "TOPOVERLAY146" (solid, pour order 0): 29.131,113.825 cw(c34,112) 29.462,114.54 29.757,114.245 ccw(c34,112) 29.56,113.825
no net on Top Overlay "TOPOVERLAY147" (solid, pour order 0): 233.743,123.755 ccw(c229.5,126) 233.94,124.175 234.369,124.175 cw(c229.5,126) 234.038,123.46
no net on Top Overlay "TOPOVERLAY148" (solid, pour order 0): 229.35,120.802 cw(c229.5,126) 224.631,124.175 225.06,124.175 ccw(c229.5,126) 229.349,121.202 229.35,121.202
no net on Top Overlay "TOPOVERLAY149" (solid, pour order 0): 233.94,127.825 ccw(c229.5,126) 229.65,130.798 229.65,131.198 cw(c229.5,126) 234.369,127.825
no net on Top Overlay "TOPOVERLAY150" (solid, pour order 0): 224.631,127.825 cw(c229.5,126) 224.962,128.54 225.257,128.245 ccw(c229.5,126) 225.06,127.825
no net on Top Overlay "TOPOVERLAY151" (solid, pour order 0): 233.743,109.755 ccw(c229.5,112) 233.94,110.175 234.369,110.175 cw(c229.5,112) 234.038,109.46
no net on Top Overlay "TOPOVERLAY152" (solid, pour order 0): 229.35,106.802 cw(c229.5,112) 224.631,110.175 225.06,110.175 ccw(c229.5,112) 229.349,107.202 229.35,107.202
no net on Top Overlay "TOPOVERLAY153" (solid, pour order 0): 233.94,113.825 ccw(c229.5,112) 229.65,116.798 229.65,117.198 cw(c229.5,112) 234.369,113.825
no net on Top Overlay "TOPOVERLAY154" (solid, pour order 0): 224.631,113.825 cw(c229.5,112) 224.962,114.54 225.257,114.245 ccw(c229.5,112) 225.06,113.825
no net on Top Overlay "TOPOVERLAY155" (solid, pour order 0): 240.131,113.825 cw(c245,112) 240.462,114.54 240.757,114.245 ccw(c245,112) 240.56,113.825
no net on Top Overlay "TOPOVERLAY156" (solid, pour order 0): 249.44,113.825 ccw(c245,112) 245.151,116.798 245.15,116.798 245.15,117.198 cw(c245,112) 249.869,113.825
no net on Top Overlay "TOPOVERLAY157" (solid, pour order 0): 244.85,106.802 cw(c245,112) 240.131,110.175 240.56,110.175 ccw(c245,112) 244.85,107.202
no net on Top Overlay "TOPOVERLAY158" (solid, pour order 0): 249.243,109.755 ccw(c245,112) 249.44,110.175 249.869,110.175 cw(c245,112) 249.538,109.46
no net on Top Overlay "TOPOVERLAY159" (solid, pour order 0): 173.743,123.755 ccw(c169.5,126) 173.94,124.175 174.369,124.175 cw(c169.5,126) 174.038,123.46
no net on Top Overlay "TOPOVERLAY160" (solid, pour order 0): 169.35,120.802 cw(c169.5,126) 164.631,124.175 165.06,124.175 ccw(c169.5,126) 169.349,121.202 169.35,121.202
no net on Top Overlay "TOPOVERLAY161" (solid, pour order 0): 173.94,127.825 ccw(c169.5,126) 169.65,130.798 169.65,131.198 cw(c169.5,126) 174.369,127.825
no net on Top Overlay "TOPOVERLAY162" (solid, pour order 0): 164.631,127.825 cw(c169.5,126) 164.962,128.54 165.257,128.245 ccw(c169.5,126) 165.06,127.825
no net on Top Overlay "TOPOVERLAY163" (solid, pour order 0): 173.743,109.755 ccw(c169.5,112) 173.94,110.175 174.369,110.175 cw(c169.5,112) 174.038,109.46
no net on Top Overlay "TOPOVERLAY164" (solid, pour order 0): 169.35,106.802 cw(c169.5,112) 164.631,110.175 165.06,110.175 ccw(c169.5,112) 169.349,107.202 169.35,107.202
no net on Top Overlay "TOPOVERLAY165" (solid, pour order 0): 173.94,113.825 ccw(c169.5,112) 169.65,116.798 169.65,117.198 cw(c169.5,112) 174.369,113.825
no net on Top Overlay "TOPOVERLAY166" (solid, pour order 0): 164.631,113.825 cw(c169.5,112) 164.962,114.54 165.257,114.245 ccw(c169.5,112) 165.06,113.825
no net on Top Overlay "TOPOVERLAY167" (solid, pour order 0): 180.131,113.825 cw(c185,112) 180.462,114.54 180.757,114.245 ccw(c185,112) 180.56,113.825
no net on Top Overlay "TOPOVERLAY168" (solid, pour order 0): 189.44,113.825 ccw(c185,112) 185.151,116.798 185.15,116.798 185.15,117.198 cw(c185,112) 189.869,113.825
no net on Top Overlay "TOPOVERLAY169" (solid, pour order 0): 184.85,106.802 cw(c185,112) 180.131,110.175 180.56,110.175 ccw(c185,112) 184.85,107.202
no net on Top Overlay "TOPOVERLAY170" (solid, pour order 0): 189.243,109.755 ccw(c185,112) 189.44,110.175 189.869,110.175 cw(c185,112) 189.538,109.46
no net on Top Overlay "TOPOVERLAY171" (solid, pour order 0): 113.743,123.755 ccw(c109.5,126) 113.94,124.175 114.369,124.175 cw(c109.5,126) 114.038,123.46
no net on Top Overlay "TOPOVERLAY172" (solid, pour order 0): 109.35,120.802 cw(c109.5,126) 104.631,124.175 105.06,124.175 ccw(c109.5,126) 109.349,121.202 109.35,121.202
no net on Top Overlay "TOPOVERLAY173" (solid, pour order 0): 113.94,127.825 ccw(c109.5,126) 109.65,130.798 109.65,131.198 cw(c109.5,126) 114.369,127.825
no net on Top Overlay "TOPOVERLAY174" (solid, pour order 0): 104.631,127.825 cw(c109.5,126) 104.962,128.54 105.257,128.245 ccw(c109.5,126) 105.06,127.825
no net on Top Overlay "TOPOVERLAY175" (solid, pour order 0): 113.743,109.755 ccw(c109.5,112) 113.94,110.175 114.369,110.175 cw(c109.5,112) 114.038,109.46
no net on Top Overlay "TOPOVERLAY176" (solid, pour order 0): 109.35,106.802 cw(c109.5,112) 104.631,110.175 105.06,110.175 ccw(c109.5,112) 109.349,107.202 109.35,107.202
no net on Top Overlay "TOPOVERLAY177" (solid, pour order 0): 113.94,113.825 ccw(c109.5,112) 109.65,116.798 109.65,117.198 cw(c109.5,112) 114.369,113.825
no net on Top Overlay "TOPOVERLAY178" (solid, pour order 0): 104.631,113.825 cw(c109.5,112) 104.962,114.54 105.257,114.245 ccw(c109.5,112) 105.06,113.825
no net on Top Overlay "TOPOVERLAY179" (solid, pour order 0): 120.131,113.825 cw(c125,112) 120.462,114.54 120.757,114.245 ccw(c125,112) 120.56,113.825
no net on Top Overlay "TOPOVERLAY180" (solid, pour order 0): 129.44,113.825 ccw(c125,112) 125.151,116.798 125.15,116.798 125.15,117.198 cw(c125,112) 129.869,113.825
no net on Top Overlay "TOPOVERLAY181" (solid, pour order 0): 124.85,106.802 cw(c125,112) 120.131,110.175 120.56,110.175 ccw(c125,112) 124.85,107.202
no net on Top Overlay "TOPOVERLAY182" (solid, pour order 0): 129.243,109.755 ccw(c125,112) 129.44,110.175 129.869,110.175 cw(c125,112) 129.538,109.46
no net on Top Overlay "TOPOVERLAY183" (solid, pour order 0): 53.743,123.755 ccw(c49.5,126) 53.94,124.175 54.369,124.175 cw(c49.5,126) 54.038,123.46
no net on Top Overlay "TOPOVERLAY184" (solid, pour order 0): 49.35,120.802 cw(c49.5,126) 44.631,124.175 45.06,124.175 ccw(c49.5,126) 49.349,121.202 49.35,121.202
no net on Top Overlay "TOPOVERLAY185" (solid, pour order 0): 53.94,127.825 ccw(c49.5,126) 49.65,130.798 49.65,131.198 cw(c49.5,126) 54.369,127.825
no net on Top Overlay "TOPOVERLAY186" (solid, pour order 0): 44.631,127.825 cw(c49.5,126) 44.962,128.54 45.257,128.245 ccw(c49.5,126) 45.06,127.825
no net on Top Overlay "TOPOVERLAY187" (solid, pour order 0): 53.743,109.755 ccw(c49.5,112) 53.94,110.175 54.369,110.175 cw(c49.5,112) 54.038,109.46
no net on Top Overlay "TOPOVERLAY188" (solid, pour order 0): 49.35,106.802 cw(c49.5,112) 44.631,110.175 45.06,110.175 ccw(c49.5,112) 49.349,107.202 49.35,107.202
no net on Top Overlay "TOPOVERLAY189" (solid, pour order 0): 53.94,113.825 ccw(c49.5,112) 49.65,116.798 49.65,117.198 cw(c49.5,112) 54.369,113.825
no net on Top Overlay "TOPOVERLAY190" (solid, pour order 0): 44.631,113.825 cw(c49.5,112) 44.962,114.54 45.257,114.245 ccw(c49.5,112) 45.06,113.825
no net on Top Overlay "TOPOVERLAY191" (solid, pour order 0): 60.131,113.825 cw(c65,112) 60.462,114.54 60.757,114.245 ccw(c65,112) 60.56,113.825
no net on Top Overlay "TOPOVERLAY192" (solid, pour order 0): 69.44,113.825 ccw(c65,112) 65.151,116.798 65.15,116.798 65.15,117.198 cw(c65,112) 69.869,113.825
no net on Top Overlay "TOPOVERLAY193" (solid, pour order 0): 64.85,106.802 cw(c65,112) 60.131,110.175 60.56,110.175 ccw(c65,112) 64.85,107.202
no net on Top Overlay "TOPOVERLAY194" (solid, pour order 0): 69.243,109.755 ccw(c65,112) 69.44,110.175 69.869,110.175 cw(c65,112) 69.538,109.46
no net on Top Overlay "TOPOVERLAY195" (solid, pour order 0): 162.6,88.2 ccw(c162.85,88.2) 163.1,88.2 ccw(c162.85,88.2)
no net on Top Overlay "TOPOVERLAY196" (solid, pour order 0): 186.8,82.85 ccw(c187.05,82.85) 187.3,82.85 ccw(c187.05,82.85)
no net on Top Overlay "TOPOVERLAY197" (solid, pour order 0): 176.8,82.85 ccw(c177.05,82.85) 177.3,82.85 ccw(c177.05,82.85)
no net on Top Overlay "TOPOVERLAY198" (solid, pour order 0): 167.175,82.85 ccw(c167.425,82.85) 167.675,82.85 ccw(c167.425,82.85)
no net on Top Overlay "TOPOVERLAY199" (solid, pour order 0): 238.025,81.05 ccw(c238.275,81.05) 238.525,81.05 ccw(c238.275,81.05)
no net on Top Overlay "TOPOVERLAY200" (solid, pour order 0): 240.35,85.45 ccw(c240.6,85.45) 240.85,85.45 ccw(c240.6,85.45)
no net on Top Overlay "TOPOVERLAY201" (solid, pour order 0): 219.75,135.825 ccw(c220,135.825) 220.25,135.825 ccw(c220,135.825)
no net on Top Overlay "TOPOVERLAY202" (solid, pour order 0): 241.75,135.825 ccw(c242,135.825) 242.25,135.825 ccw(c242,135.825)
no net on Top Overlay "TOPOVERLAY203" (solid, pour order 0): 255.75,135.825 ccw(c256,135.825) 256.25,135.825 ccw(c256,135.825)
no net on Top Overlay "TOPOVERLAY204" (solid, pour order 0): 257.55,125.9 ccw(c257.8,125.9) 258.05,125.9 ccw(c257.8,125.9)
no net on Top Overlay "TOPOVERLAY205" (solid, pour order 0): 166.75,135.825 ccw(c167,135.825) 167.25,135.825 ccw(c167,135.825)
no net on Top Overlay "TOPOVERLAY206" (solid, pour order 0): 189.75,135.825 ccw(c190,135.825) 190.25,135.825 ccw(c190,135.825)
